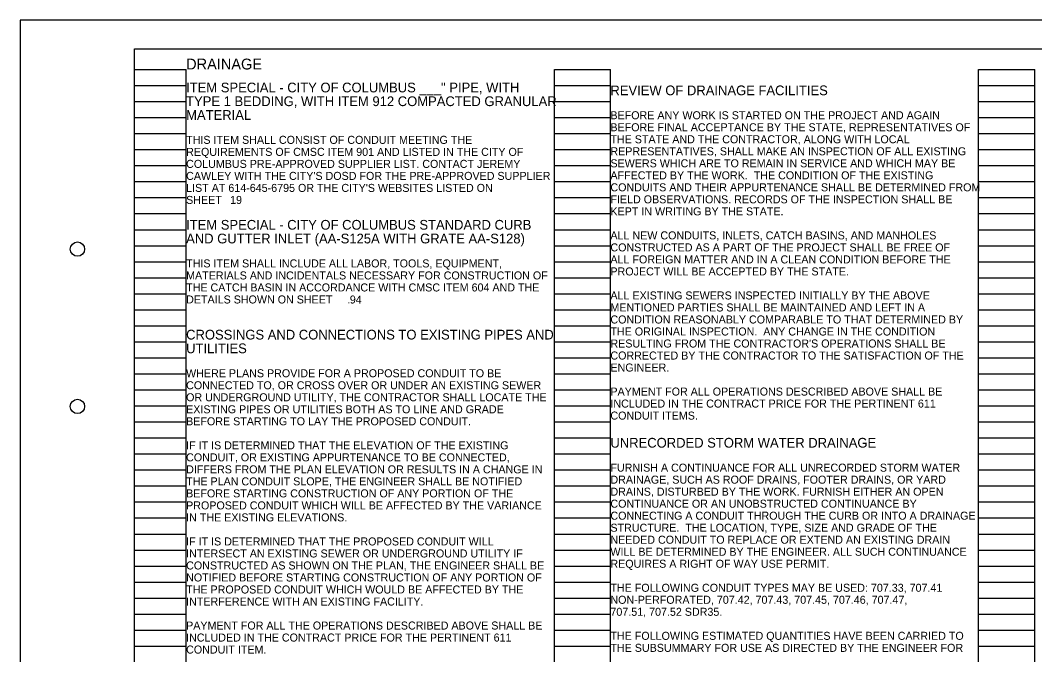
# Model space of a CAD drawing. Extents: x 0 to 34, y 0 to 22.
# Drawn here: x 0 to 17.74, y 10.91 to 22 of the extents above; entities that cross this region are included whole.
import ezdxf

# ---------------------------------------------------------------- set-up
doc = ezdxf.new("R2010")
doc.units = 0
for name, color, linetype in [('SC_Scratch1', 7, 'Continuous'), ('SH_Border', 7, 'Continuous'), ('SH_Cut_Line', 7, 'Continuous'), ('SH_Data', 7, 'Continuous'), ('SH_Text', 7, 'Continuous'), ('TX_P_1', 7, 'Continuous'), ('TX_P_Misc', 7, 'Continuous')]:
    doc.layers.add(name, color=color, linetype=linetype)

msp = doc.modelspace()

# ---------------------------------------------------------------- linework, layer by layer
at = {"layer": 'SC_Scratch1'}
for p, q in [((2, 0.98), (2, 21.14)), ((2, 21.14), (2.9, 21.14)), ((2.9, 0.98), (2.9, 21.14)), ((9.34, 0.98), (9.34, 21.14)), ((9.34, 21.14), (10.32, 21.14)), ((10.32, 0.98), (10.32, 21.14)), ((16.76, 0.98), (16.76, 21.14)), ((16.76, 21.14), (17.74, 21.14)), ((17.74, 0.98), (17.74, 21.14)), ((2, 20.86), (2.9, 20.86)), ((9.34, 20.86), (10.32, 20.86)), ((16.76, 20.86), (17.74, 20.86)), ((2, 20.58), (2.9, 20.58)), ((9.34, 20.58), (10.32, 20.58)), ((16.76, 20.58), (17.74, 20.58)), ((2, 20.3), (2.9, 20.3)), ((9.34, 20.3), (10.32, 20.3)), ((16.76, 20.3), (17.74, 20.3)), ((2, 20.02), (2.9, 20.02)), ((9.34, 20.02), (10.32, 20.02)), ((16.76, 20.02), (17.74, 20.02)), ((2, 19.74), (2.9, 19.74)), ((9.34, 19.74), (10.32, 19.74)), ((16.76, 19.74), (17.74, 19.74)), ((2, 19.46), (2.9, 19.46)), ((9.34, 19.46), (10.32, 19.46)), ((16.76, 19.46), (17.74, 19.46)), ((2, 19.18), (2.9, 19.18)), ((9.34, 19.18), (10.32, 19.18)), ((16.76, 19.18), (17.74, 19.18)), ((2, 18.9), (2.9, 18.9)), ((9.34, 18.9), (10.32, 18.9)), ((16.76, 18.9), (17.74, 18.9)), ((2, 18.62), (2.9, 18.62)), ((9.34, 18.62), (10.32, 18.62)), ((16.76, 18.62), (17.74, 18.62)), ((2, 18.34), (2.9, 18.34)), ((9.34, 18.34), (10.32, 18.34)), ((16.76, 18.34), (17.74, 18.34)), ((2, 18.06), (2.9, 18.06)), ((9.34, 18.06), (10.32, 18.06)), ((16.76, 18.06), (17.74, 18.06)), ((2, 17.78), (2.9, 17.78)), ((9.34, 17.78), (10.32, 17.78)), ((16.76, 17.78), (17.74, 17.78)), ((2, 17.5), (2.9, 17.5)), ((9.34, 17.5), (10.32, 17.5)), ((16.76, 17.5), (17.74, 17.5)), ((2, 17.22), (2.9, 17.22)), ((9.34, 17.22), (10.32, 17.22)), ((16.76, 17.22), (17.74, 17.22)), ((2, 16.94), (2.9, 16.94)), ((9.34, 16.94), (10.32, 16.94)), ((16.76, 16.94), (17.74, 16.94)), ((2, 16.66), (2.9, 16.66)), ((9.34, 16.66), (10.32, 16.66)), ((16.76, 16.66), (17.74, 16.66)), ((2, 16.38), (2.9, 16.38)), ((9.34, 16.38), (10.32, 16.38)), ((16.76, 16.38), (17.74, 16.38)), ((2, 16.1), (2.9, 16.1)), ((9.34, 16.1), (10.32, 16.1)), ((16.76, 16.1), (17.74, 16.1)), ((2, 15.82), (2.9, 15.82)), ((9.34, 15.82), (10.32, 15.82)), ((16.76, 15.82), (17.74, 15.82)), ((2, 15.54), (2.9, 15.54)), ((9.34, 15.54), (10.32, 15.54)), ((16.76, 15.54), (17.74, 15.54)), ((2, 15.26), (2.9, 15.26)), ((9.34, 15.26), (10.32, 15.26)), ((16.76, 15.26), (17.74, 15.26)), ((2, 14.98), (2.9, 14.98)), ((9.34, 14.98), (10.32, 14.98)), ((16.76, 14.98), (17.74, 14.98)), ((2, 14.7), (2.9, 14.7)), ((9.34, 14.7), (10.32, 14.7)), ((16.76, 14.7), (17.74, 14.7)), ((2, 14.42), (2.9, 14.42)), ((9.34, 14.42), (10.32, 14.42)), ((16.76, 14.42), (17.74, 14.42)), ((2, 14.14), (2.9, 14.14)), ((9.34, 14.14), (10.32, 14.14)), ((16.76, 14.14), (17.74, 14.14)), ((2, 13.86), (2.9, 13.86)), ((9.34, 13.86), (10.32, 13.86)), ((16.76, 13.86), (17.74, 13.86)), ((2, 13.58), (2.9, 13.58)), ((9.34, 13.58), (10.32, 13.58)), ((16.76, 13.58), (17.74, 13.58)), ((2, 13.3), (2.9, 13.3)), ((9.34, 13.3), (10.32, 13.3)), ((16.76, 13.3), (17.74, 13.3)), ((2, 13.02), (2.9, 13.02)), ((9.34, 13.02), (10.32, 13.02)), ((16.76, 13.02), (17.74, 13.02)), ((2, 12.74), (2.9, 12.74)), ((9.34, 12.74), (10.32, 12.74)), ((16.76, 12.74), (17.74, 12.74)), ((2, 12.46), (2.9, 12.46)), ((9.34, 12.46), (10.32, 12.46)), ((16.76, 12.46), (17.74, 12.46)), ((2, 12.18), (2.9, 12.18)), ((9.34, 12.18), (10.32, 12.18)), ((16.76, 12.18), (17.74, 12.18)), ((2, 11.9), (2.9, 11.9)), ((9.34, 11.9), (10.32, 11.9)), ((16.76, 11.9), (17.74, 11.9)), ((2, 11.62), (2.9, 11.62)), ((9.34, 11.62), (10.32, 11.62)), ((16.76, 11.62), (17.74, 11.62)), ((2, 11.34), (2.9, 11.34)), ((9.34, 11.34), (10.32, 11.34)), ((16.76, 11.34), (17.74, 11.34)), ((2, 11.06), (2.9, 11.06)), ((9.34, 11.06), (10.32, 11.06)), ((16.76, 11.06), (17.74, 11.06))]:
    msp.add_line(p, q, dxfattribs=at)
at = {"layer": 'SH_Border'}
msp.add_lwpolyline([(2, 21.5), (33.5, 21.5), (33.5, 0.5), (2, 0.5)], close=True, dxfattribs=at)
for centre in [(1, 18), (1, 15.25)]:
    msp.add_circle(centre, 0.125, dxfattribs=at)
at = {"layer": 'SH_Cut_Line'}
msp.add_lwpolyline([(0, 0), (34, 0), (34, 22), (0, 22)], close=True, dxfattribs=at)

# ---------------------------------------------------------------- texts
at = {"layer": 'SH_Data'}
msp.add_text('94', height=0.14, dxfattribs=at).set_placement((5.763, 17.049))
at = {"layer": 'SH_Text'}
for s, p in [('BEFORE ANY WORK IS STARTED ON THE PROJECT AND AGAIN ', (10.32, 20.27)), ('BEFORE FINAL ACCEPTANCE BY THE STATE, REPRESENTATIVES OF ', (10.32, 20.06)), ('THIS ITEM SHALL CONSIST OF CONDUIT MEETING THE ', (2.9, 19.84)), ('THE STATE AND THE CONTRACTOR, ALONG WITH LOCAL ', (10.32, 19.85)), ('REQUIREMENTS OF CMSC ITEM 901 AND LISTED IN THE CITY OF ', (2.9, 19.63)), ('REPRESENTATIVES, SHALL MAKE AN INSPECTION OF ALL EXISTING ', (10.32, 19.64)), ('COLUMBUS PRE-APPROVED SUPPLIER LIST. CONTACT JEREMY ', (2.9, 19.42)), ('SEWERS WHICH ARE TO REMAIN IN SERVICE AND WHICH MAY BE ', (10.32, 19.43)), ("CAWLEY WITH THE CITY'S DOSD FOR THE PRE-APPROVED SUPPLIER ", (2.9, 19.21)), ('AFFECTED BY THE WORK.  THE CONDITION OF THE EXISTING ', (10.32, 19.22)), ("LIST AT 614-645-6795 OR THE CITY'S WEBSITES LISTED ON ", (2.9, 19)), ('CONDUITS AND THEIR APPURTENANCE SHALL BE DETERMINED FROM ', (10.32, 19.01)), ('SHEET    .', (2.9, 18.79)), ('19', (3.669, 18.79)), ('FIELD OBSERVATIONS. RECORDS OF THE INSPECTION SHALL BE ', (10.32, 18.8)), ('KEPT IN WRITING BY THE STATE. ', (10.32, 18.59)), ('ALL NEW CONDUITS, INLETS, CATCH BASINS, AND MANHOLES ', (10.32, 18.17)), ('CONSTRUCTED AS A PART OF THE PROJECT SHALL BE FREE OF ', (10.32, 17.96)), ('THIS ITEM SHALL INCLUDE ALL LABOR, TOOLS, EQUIPMENT, ', (2.9, 17.68)), ('ALL FOREIGN MATTER AND IN A CLEAN CONDITION BEFORE THE ', (10.32, 17.75)), ('MATERIALS AND INCIDENTALS NECESSARY FOR CONSTRUCTION OF ', (2.9, 17.47)), ('PROJECT WILL BE ACCEPTED BY THE STATE.', (10.32, 17.54)), ('THE CATCH BASIN IN ACCORDANCE WITH CMSC ITEM 604 AND THE ', (2.9, 17.26)), ('ALL EXISTING SEWERS INSPECTED INITIALLY BY THE ABOVE ', (10.32, 17.12)), ('DETAILS SHOWN ON SHEET     .', (2.9, 17.05)), ('MENTIONED PARTIES SHALL BE MAINTAINED AND LEFT IN A ', (10.32, 16.91)), ('CONDITION REASONABLY COMPARABLE TO THAT DETERMINED BY ', (10.32, 16.7)), ('THE ORIGINAL INSPECTION.  ANY CHANGE IN THE CONDITION ', (10.32, 16.49)), ("RESULTING FROM THE CONTRACTOR'S OPERATIONS SHALL BE ", (10.32, 16.28)), ('CORRECTED BY THE CONTRACTOR TO THE SATISFACTION OF THE ', (10.32, 16.07)), ('ENGINEER.', (10.32, 15.86)), ('WHERE PLANS PROVIDE FOR A PROPOSED CONDUIT TO BE ', (2.9, 15.76)), ('CONNECTED TO, OR CROSS OVER OR UNDER AN EXISTING SEWER ', (2.9, 15.55)), ('OR UNDERGROUND UTILITY, THE CONTRACTOR SHALL LOCATE THE ', (2.9, 15.34)), ('PAYMENT FOR ALL OPERATIONS DESCRIBED ABOVE SHALL BE ', (10.32, 15.44)), ('EXISTING PIPES OR UTILITIES BOTH AS TO LINE AND GRADE ', (2.9, 15.13)), ('INCLUDED IN THE CONTRACT PRICE FOR THE PERTINENT 611 ', (10.32, 15.23)), ('CONDUIT ITEMS.', (10.32, 15.02)), ('BEFORE STARTING TO LAY THE PROPOSED CONDUIT.', (2.9, 14.92)), ('IF IT IS DETERMINED THAT THE ELEVATION OF THE EXISTING ', (2.9, 14.5)), ('CONDUIT, OR EXISTING APPURTENANCE TO BE CONNECTED, ', (2.9, 14.29)), ('DIFFERS FROM THE PLAN ELEVATION OR RESULTS IN A CHANGE IN ', (2.9, 14.08)), ('FURNISH A CONTINUANCE FOR ALL UNRECORDED STORM WATER ', (10.32, 14.11)), ('DRAINAGE, SUCH AS ROOF DRAINS, FOOTER DRAINS, OR YARD ', (10.32, 13.9)), ('THE PLAN CONDUIT SLOPE, THE ENGINEER SHALL BE NOTIFIED ', (2.9, 13.87)), ('BEFORE STARTING CONSTRUCTION OF ANY PORTION OF THE ', (2.9, 13.66)), ('DRAINS, DISTURBED BY THE WORK. FURNISH EITHER AN OPEN ', (10.32, 13.69)), ('PROPOSED CONDUIT WHICH WILL BE AFFECTED BY THE VARIANCE ', (2.9, 13.45)), ('CONTINUANCE OR AN UNOBSTRUCTED CONTINUANCE BY ', (10.32, 13.48)), ('IN THE EXISTING ELEVATIONS.', (2.9, 13.24)), ('CONNECTING A CONDUIT THROUGH THE CURB OR INTO A DRAINAGE ', (10.32, 13.27)), ('STRUCTURE.  THE LOCATION, TYPE, SIZE AND GRADE OF THE ', (10.32, 13.06)), ('IF IT IS DETERMINED THAT THE PROPOSED CONDUIT WILL ', (2.9, 12.82)), ('NEEDED CONDUIT TO REPLACE OR EXTEND AN EXISTING DRAIN ', (10.32, 12.85)), ('WILL BE DETERMINED BY THE ENGINEER. ALL SUCH CONTINUANCE ', (10.32, 12.64)), ('INTERSECT AN EXISTING SEWER OR UNDERGROUND UTILITY IF ', (2.9, 12.61)), ('CONSTRUCTED AS SHOWN ON THE PLAN, THE ENGINEER SHALL BE ', (2.9, 12.4)), ('REQUIRES A RIGHT OF WAY USE PERMIT.', (10.32, 12.43)), ('NOTIFIED BEFORE STARTING CONSTRUCTION OF ANY PORTION OF ', (2.9, 12.19)), ('THE PROPOSED CONDUIT WHICH WOULD BE AFFECTED BY THE ', (2.9, 11.98)), ('THE FOLLOWING CONDUIT TYPES MAY BE USED: 707.33, 707.41 ', (10.32, 12.01)), ('INTERFERENCE WITH AN EXISTING FACILITY.', (2.9, 11.77)), ('NON-PERFORATED, 707.42, 707.43, 707.45, 707.46, 707.47, ', (10.32, 11.8)), ('707.51, 707.52 SDR35.', (10.32, 11.59)), ('PAYMENT FOR ALL THE OPERATIONS DESCRIBED ABOVE SHALL BE ', (2.9, 11.35)), ('INCLUDED IN THE CONTRACT PRICE FOR THE PERTINENT 611 ', (2.9, 11.14)), ('THE FOLLOWING ESTIMATED QUANTITIES HAVE BEEN CARRIED TO ', (10.32, 11.17)), ('CONDUIT ITEM.', (2.9, 10.93)), ('THE SUBSUMMARY FOR USE AS DIRECTED BY THE ENGINEER FOR ', (10.32, 10.96))]:
    msp.add_text(s, height=0.14, dxfattribs=at).set_placement(p)
at = {"layer": 'TX_P_1'}
msp.add_text('DRAINAGE', height=0.19, dxfattribs=at).set_placement((2.9, 21.14))
at = {"layer": 'TX_P_Misc'}
for s, p in [('ITEM SPECIAL - CITY OF COLUMBUS ___" PIPE, WITH ', (2.9, 20.74)), ('REVIEW OF DRAINAGE FACILITIES', (10.32, 20.69)), ('TYPE 1 BEDDING, WITH ITEM 912 COMPACTED GRANULAR ', (2.9, 20.5)), ('MATERIAL', (2.9, 20.26)), ('ITEM SPECIAL - CITY OF COLUMBUS STANDARD CURB ', (2.9, 18.34)), ('AND GUTTER INLET (AA-S125A WITH GRATE AA-S128)', (2.9, 18.1)), ('CROSSINGS AND CONNECTIONS TO EXISTING PIPES AND ', (2.9, 16.42)), ('UTILITIES', (2.9, 16.18)), ('UNRECORDED STORM WATER DRAINAGE', (10.32, 14.53))]:
    msp.add_text(s, height=0.17, dxfattribs=at).set_placement(p)

doc.saveas('drawing.dxf')
